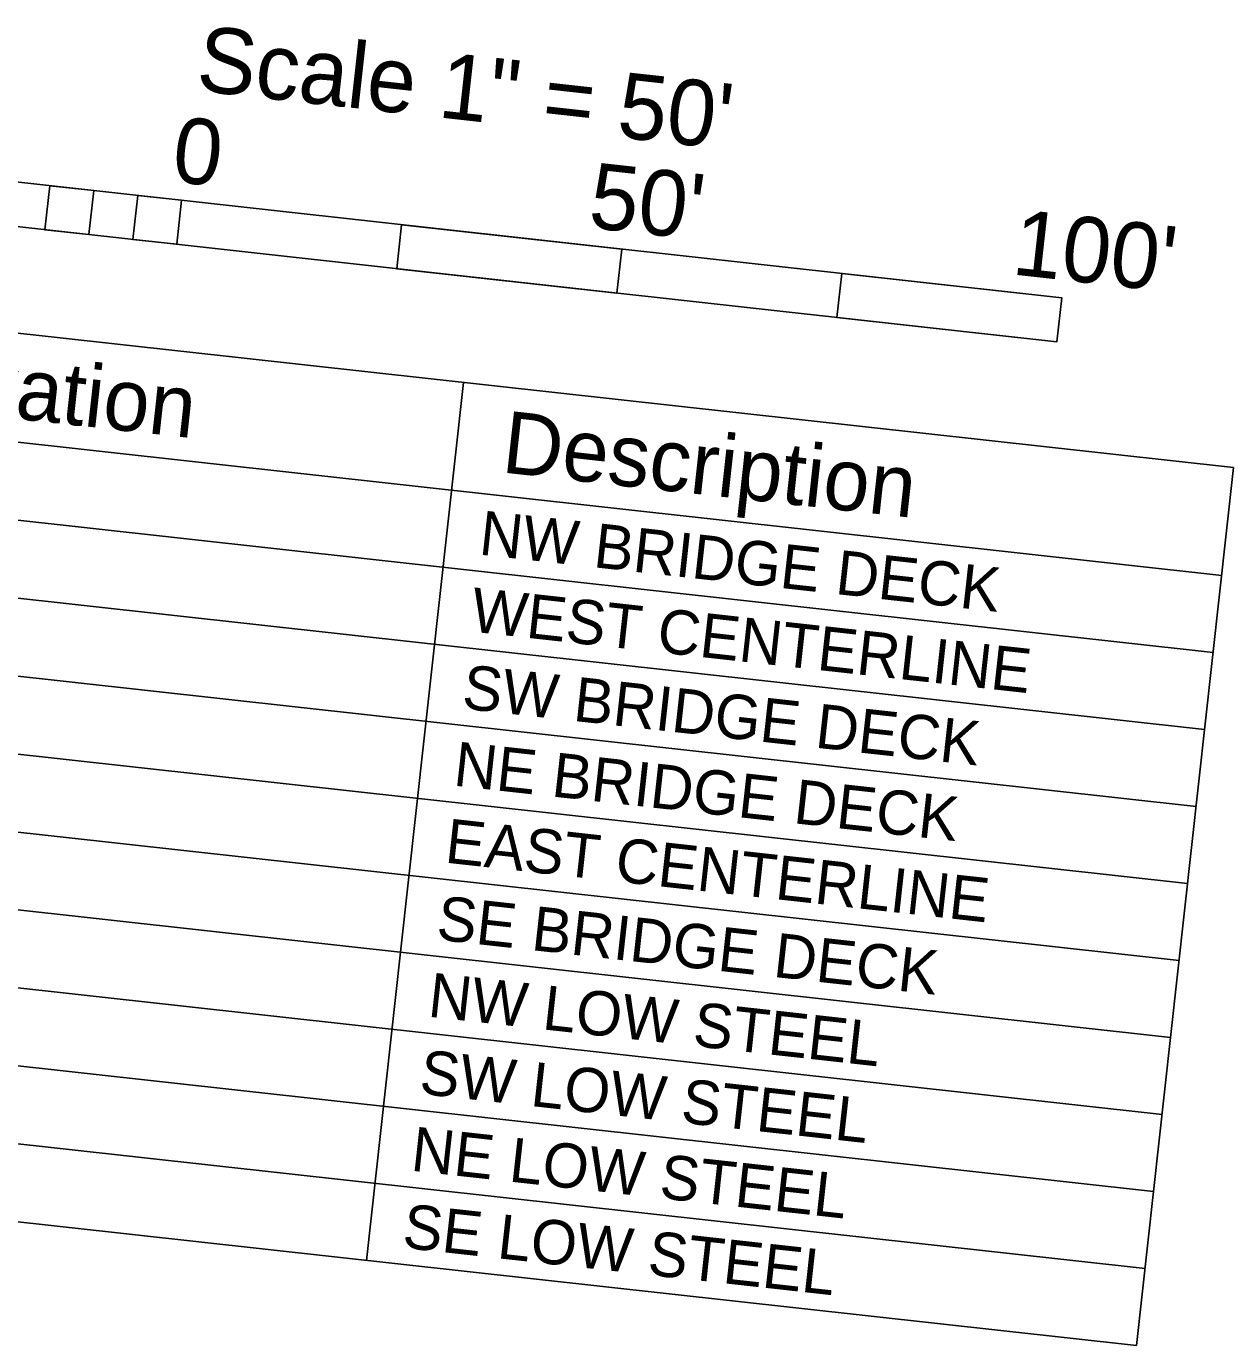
# Model space of a CAD drawing. Extents: x 1150279 to 1151282, y 654632 to 657999.
# Drawn here: x 1150909.2 to 1151045.5, y 656828.1 to 656977 of the extents above; entities that cross this region are included whole.
import ezdxf

# ---------------------------------------------------------------- set-up
doc = ezdxf.new("R2010")
doc.units = 0
doc.layers.add('CTL Sheet Datum Description CELL', color=7, linetype='Continuous')
doc.layers.add('Exist Other Culture Located Object Text', color=7, linetype='Continuous')

msp = doc.modelspace()

# ---------------------------------------------------------------- linework, layer by layer
at = {"layer": 'CTL Sheet Datum Description CELL'}
for points in [[(1150876.48, 656957.93), (1151025.57, 656941.43), (1151026.12, 656946.4), (1150877.03, 656962.9)], [(1150911.27, 656954.08), (1150916.24, 656953.53), (1150916.79, 656958.5), (1150911.82, 656959.05)], [(1150921.21, 656952.98), (1150926.18, 656952.43), (1150926.72, 656957.4), (1150921.76, 656957.95)], [(1150951.02, 656949.68), (1150975.87, 656946.93), (1150976.42, 656951.9), (1150951.57, 656954.65)], [(1151000.72, 656944.18), (1151025.57, 656941.43), (1151026.12, 656946.4), (1151001.27, 656949.15)]]:
    msp.add_lwpolyline(points, close=True, dxfattribs=at)
at = {"layer": 'Exist Other Culture Located Object Text'}
for p, q in [((1150711.08, 656964.22), (1151045.54, 656927.21)), ((1150709.73, 656952.04), (1151044.19, 656915.04)), ((1150708.77, 656943.34), (1151043.23, 656906.34)), ((1150708.77, 656943.34), (1151043.23, 656906.34)), ((1150708.77, 656943.34), (1151043.23, 656906.34)), ((1150708.77, 656943.34), (1151043.23, 656906.34)), ((1150708.77, 656943.34), (1151043.23, 656906.34)), ((1150958.57, 656936.83), (1150951.45, 656872.48)), ((1150707.8, 656934.65), (1151042.26, 656897.64)), ((1150707.8, 656934.65), (1151042.26, 656897.64)), ((1150707.8, 656934.65), (1151042.26, 656897.64)), ((1150707.8, 656934.65), (1151042.26, 656897.64)), ((1150707.8, 656934.65), (1151042.26, 656897.64)), ((1151045.54, 656927.21), (1151038.42, 656862.86)), ((1150706.84, 656925.95), (1151041.3, 656888.95)), ((1150706.84, 656925.95), (1151041.3, 656888.95)), ((1150706.84, 656925.95), (1151041.3, 656888.95)), ((1150706.84, 656925.95), (1151041.3, 656888.95)), ((1150706.84, 656925.95), (1151041.3, 656888.95)), ((1150705.88, 656917.25), (1151040.34, 656880.25)), ((1150705.88, 656917.25), (1151040.34, 656880.25)), ((1150705.88, 656917.25), (1151040.34, 656880.25)), ((1150705.88, 656917.25), (1151040.34, 656880.25)), ((1150705.88, 656917.25), (1151040.34, 656880.25)), ((1150704.92, 656908.56), (1151039.38, 656871.55)), ((1150704.92, 656908.56), (1151039.38, 656871.55)), ((1150704.92, 656908.56), (1151039.38, 656871.55)), ((1150704.92, 656908.56), (1151039.38, 656871.55)), ((1150704.92, 656908.56), (1151039.38, 656871.55)), ((1150703.96, 656899.86), (1151038.42, 656862.86)), ((1150703.96, 656899.86), (1151038.42, 656862.86)), ((1150703.96, 656899.86), (1151038.42, 656862.86)), ((1150703.96, 656899.86), (1151038.42, 656862.86)), ((1150703.96, 656899.86), (1151038.42, 656862.86)), ((1150702.99, 656891.16), (1151037.45, 656854.16)), ((1150702.99, 656891.16), (1151037.45, 656854.16)), ((1150702.99, 656891.16), (1151037.45, 656854.16)), ((1150702.99, 656891.16), (1151037.45, 656854.16)), ((1150702.99, 656891.16), (1151037.45, 656854.16)), ((1150702.03, 656882.46), (1151036.49, 656845.46)), ((1150702.03, 656882.46), (1151036.49, 656845.46)), ((1150702.03, 656882.46), (1151036.49, 656845.46)), ((1150702.03, 656882.46), (1151036.49, 656845.46)), ((1150702.03, 656882.46), (1151036.49, 656845.46)), ((1150701.07, 656873.77), (1151035.53, 656836.76)), ((1150701.07, 656873.77), (1151035.53, 656836.76)), ((1150701.07, 656873.77), (1151035.53, 656836.76)), ((1150701.07, 656873.77), (1151035.53, 656836.76)), ((1150701.07, 656873.77), (1151035.53, 656836.76)), ((1150951.45, 656872.48), (1150947.6, 656837.69)), ((1150700.11, 656865.07), (1151034.57, 656828.07)), ((1150700.11, 656865.07), (1151034.57, 656828.07)), ((1150700.11, 656865.07), (1151034.57, 656828.07)), ((1150700.11, 656865.07), (1151034.57, 656828.07)), ((1150700.11, 656865.07), (1151034.57, 656828.07)), ((1151038.42, 656862.86), (1151034.57, 656828.07))]:
    msp.add_line(p, q, dxfattribs=at)

# ---------------------------------------------------------------- texts
at = {"layer": 'CTL Sheet Datum Description CELL'}
for s, p in [('Scale 1" = 50\'', (1150928.22, 656969.81)), ('0', (1150925.44, 656959.55)), ("50'", (1150972.51, 656954.34)), ("100'", (1151020.36, 656949.05))]:
    msp.add_text(s, height=7.4, rotation=353.6867, dxfattribs=at).set_placement(p)
at = {"layer": 'Exist Other Culture Located Object Text'}
for s, height, p in [('Elevation', 7, (1150889.67, 656934.77)), ('Description', 7, (1150962.73, 656926.69)), ('NW BRIDGE DECK', 5, (1150960.19, 656917.41)), ('WEST CENTERLINE', 5, (1150959.23, 656908.72)), ('SW BRIDGE DECK', 5, (1150958.27, 656900.02)), ('NE BRIDGE DECK', 5, (1150957.3, 656891.32)), ('EAST CENTERLINE', 5, (1150956.34, 656882.63)), ('SE BRIDGE DECK', 5, (1150955.38, 656873.93)), ('NW LOW STEEL', 5, (1150954.42, 656865.23)), ('SW LOW STEEL', 5, (1150953.45, 656856.53)), ('NE LOW STEEL', 5, (1150952.49, 656847.84)), ('SE LOW STEEL', 5, (1150951.53, 656839.14))]:
    msp.add_text(s, height=height, rotation=353.6867, dxfattribs=at).set_placement(p)

doc.saveas('drawing.dxf')
